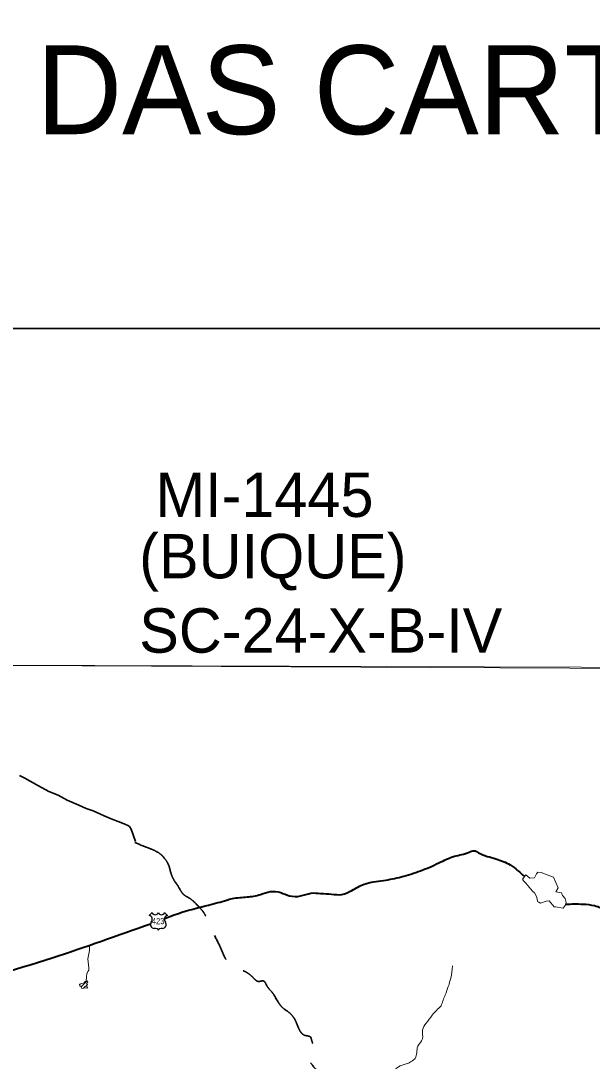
# Model space of a CAD drawing. Extents: x 553962 to 842807, y 8883888 to 9032388.
# Drawn here: x 599099 to 605530, y 8916524 to 8928234 of the extents above; entities that cross this region are included whole.
import ezdxf
from ezdxf.enums import TextEntityAlignment as Align

# ---------------------------------------------------------------- set-up
doc = ezdxf.new("R2010")
doc.units = 0
doc.header["$LTSCALE"] = 200
doc.linetypes.add('LONG_DASH_SHORT_DASH', pattern=[9.9, 6, -1.2, 1.5, -1.2])
doc.layers.add('6', color=7, linetype='Continuous', lineweight=13)

msp = doc.modelspace()

# ---------------------------------------------------------------- linework, layer by layer
at = {"layer": '6', "lineweight": 25}
for p, q in [((600544.7, 8918164.1), (600576.6, 8918196.1)), ((600716.5, 8918196.1), (600748.5, 8918164.1))]:
    msp.add_line(p, q, dxfattribs=at)
at = {"layer": '6'}
for p, q in [((599760.1, 8917384.1), (599770.4, 8917394.5)), ((599779.1, 8917360.8), (599843, 8917424.7)), ((599804.6, 8917343.8), (599848.1, 8917387.3)), ((599850.7, 8917347.5), (599851.7, 8917348.5))]:
    msp.add_line(p, q, dxfattribs=at)
at = {"layer": '6', "lineweight": 35}
msp.add_lwpolyline([(574695.3, 8924769.6), (626625.7, 8924769.6), (626625.7, 8896026.7), (574695.3, 8896026.7)], close=True, dxfattribs=at)
at = {"layer": '6'}
for points in [[(574684.9, 8921064.7), (596639.8, 8920989.8), (607636.3, 8920937.2), (626625.7, 8920820.5)], [(599871, 8917832.6), (599871.8, 8917767.7), (599854.5, 8917674.6), (599859.5, 8917608.7), (599864.6, 8917573), (599864.4, 8917548.3), (599853.3, 8917532), (599842.1, 8917507.4), (599836.4, 8917477.3), (599835.9, 8917422.3)]]:
    msp.add_lwpolyline(points, dxfattribs=at)
for points in [[(607600.8, 8920952.4), (596639.8, 8920989.8), (596608.8, 8909934.4), (607569.8, 8909894.9)], [(604784, 8918621.1), (604829.4, 8918582.7), (604881.8, 8918586.2), (604904.5, 8918633.3), (604918.5, 8918650.8), (604955.1, 8918647.3), (605023.2, 8918621.1), (605094.8, 8918593.2), (605145.5, 8918476.1), (605122.8, 8918430.7), (605183.9, 8918418.4), (605194.4, 8918387), (605225.8, 8918353.8), (605236.3, 8918310.1), (605227.6, 8918275.2), (605204.9, 8918247.2), (605115.8, 8918259.5), (605101.8, 8918261.2), (605044.2, 8918329.3), (605011, 8918325.8), (604949.9, 8918303.1), (604928.9, 8918311.9), (604913.2, 8918322.4), (604908, 8918371.3), (604880, 8918418.4), (604859.1, 8918435.9), (604784, 8918528.5), (604756, 8918553), (604745.5, 8918572.2)], [(599850.5, 8917427.2), (599834.3, 8917421.8), (599821.6, 8917421.3), (599813.8, 8917417.5), (599813.2, 8917405.3), (599758.2, 8917391.4), (599764.6, 8917366.4), (599775.7, 8917369.7), (599787.1, 8917340.2), (599836, 8917350.3), (599843.2, 8917350.2), (599852.5, 8917346.8), (599837.8, 8917375.8), (599849.5, 8917384.5), (599839.7, 8917403.4), (599853.1, 8917410)]]:
    msp.add_lwpolyline(points, close=True, dxfattribs=at)
at = {"layer": '6', "linetype": 'LONG_DASH_SHORT_DASH', "lineweight": 35}
msp.add_lwpolyline([(599084.4, 8919739.6), (599142.2, 8919708.2), (599298.2, 8919621.7), (599412.6, 8919560.7), (599519.3, 8919519.8), (599620.2, 8919462.1), (599750.1, 8919406.2), (599835.6, 8919368), (599912.8, 8919340.3), (600036.8, 8919285), (600114.6, 8919250.2), (600193.7, 8919219.8), (600262.6, 8919196), (600311.4, 8919174.3), (600323, 8919165.1), (600340.1, 8919135.3), (600389.9, 8918996.8)], dxfattribs=at)
at = {"layer": '6', "lineweight": 25}
for centre, radius, start, end in [((600611.6, 8918209.5), 37.4, 200.95927, 339.04073), ((600681.5, 8918209.5), 37.4, 200.95927, 339.04073), ((600532.2, 8918119.7), 46.1, 317.5721, 74.36886), ((600602.9, 8918062.7), 44.9, 144.73733, 264.65778), ((600690.2, 8918062.7), 44.9, 275.34222, 35.26267), ((600760.9, 8918119.7), 46.1, 105.62774, 222.4279), ((600598.5, 8917900), 118, 72.89371, 89.90057), ((600627.7, 8917994.7), 18.9, 357.69345, 72.92955), ((600665.4, 8917994.7), 18.9, 107.07045, 182.30655), ((600694.6, 8917900), 118, 90.09943, 107.10629)]:
    msp.add_arc(centre, radius, start, end, dxfattribs=at)
at = {"layer": '6', "lineweight": 40}
for points in [[(605233.4, 8918291.8), (605425.1, 8918291.8), (605556.8, 8918274.6), (605694.1, 8918217.3), (605780, 8918168.6), (605911.6, 8918165.8), (606008.9, 8918211.6), (606114.8, 8918211.6), (606197.8, 8918134.3), (606353.7, 8918138.6), (606551.2, 8918198.7), (606637.1, 8918198.7), (606903.2, 8918104.2), (607195.1, 8918130), (607418.3, 8918172.9), (607555.7, 8918130), (607658.7, 8918138.6), (607753.1, 8918172.9), (607813.2, 8918172.9), (607967.8, 8918353.3), (608139.5, 8918542.3), (608208.1, 8918748.4), (608345.5, 8918868.7), (608508.6, 8918946), (608680.3, 8919186.5), (608766.2, 8919298.2), (608826.3, 8919384.1), (608920.7, 8919409.8), (609058.1, 8919427), (609126.8, 8919444.2), (609186.8, 8919512.9), (609272.7, 8919538.7), (609418.7, 8919530.1), (609633.3, 8919581.6), (609805, 8919650.3), (609950.9, 8919727.6), (610174.2, 8919847.9), (610285.8, 8919890.8), (610500.4, 8919959.5), (610612, 8920002.5), (610715, 8920002.5), (610989.7, 8919925.2)], [(601410.6, 8918334.5), (601480.5, 8918354.8), (601646.5, 8918371.9), (601798.2, 8918400.6), (601906.9, 8918432.1), (602024.2, 8918420.6), (602124.4, 8918386.2), (602247.5, 8918383.4), (602364.8, 8918414.9), (602473.5, 8918412), (602596.6, 8918403.4), (602713.9, 8918400.6), (602825.5, 8918446.4), (602962.9, 8918515.1), (603180.4, 8918558), (603380.7, 8918598.1), (603598.2, 8918666.8), (603804.2, 8918755.6), (603978.8, 8918830), (604145.9, 8918875.8), (604200.3, 8918893), (604251.8, 8918870.1), (604446.4, 8918801.4), (604606.7, 8918732.7), (604769.8, 8918601)], [(600716.1, 8918129.4), (600909.4, 8918199.2), (601211.8, 8918280.7), (601418.4, 8918336.7)], [(596244.3, 8916699.1), (596768.6, 8916837.7), (598135.3, 8917279.9), (599449.7, 8917687.2), (600558.2, 8918071.1)]]:
    msp.add_spline(points, degree=3, dxfattribs=at)
at = {"layer": '6', "linetype": 'LONG_DASH_SHORT_DASH', "lineweight": 35}
msp.add_spline([(600381.6, 8918983.9), (600541.4, 8918921.3), (600673.5, 8918851.8), (600729.1, 8918789.3), (600763.8, 8918726.8), (600791.6, 8918629.5), (600819.4, 8918566.9), (600875, 8918483.6), (600930.6, 8918400.2), (601007, 8918351.5), (601076.5, 8918289), (601146, 8918212.6), (601243.3, 8918011), (601326.7, 8917844.3), (601389.2, 8917705.3), (601458.7, 8917601.1), (601549, 8917559.4), (601625.5, 8917531.6), (601715.8, 8917462.1), (601778.3, 8917420.4), (601827, 8917427.3), (601868.7, 8917371.8), (601924.2, 8917302.3), (602042.4, 8917128.5), (602132.7, 8917059.1), (602195.3, 8916968.7), (602237, 8916871.4), (602293.6, 8916815.3), (602362.3, 8916791.5), (602370.9, 8916763.8), (602382.4, 8916729.4), (602386.2, 8916632), (602375.9, 8916614.3), (602341.3, 8916526), (602362, 8916503.2), (602415.8, 8916437.2), (602443.5, 8916415.3), (602473.2, 8916343.3), (602487.1, 8916183.5), (602501, 8916086.2), (602528.4, 8916025.6), (602570.4, 8915982.6), (602548.4, 8915898.7), (602535.1, 8915867.2), (602486.4, 8915817.5), (602441.6, 8915736.4), (602464.5, 8915679.2), (602557, 8915738.3), (602710.7, 8915862.4), (602741.2, 8915892.9), (602862.4, 8915972.1), (603008.4, 8916103.8), (603086.7, 8916151.5), (603209.8, 8916155.7), (603293.2, 8916155.7)], degree=3, dxfattribs=at)
at = {"layer": '6'}
for points in [[(603828.9, 8917146.1), (603875.9, 8917271.5), (603938.5, 8917459.6), (603959.4, 8917595.5)], [(601609.2, 8914720.1), (601610.4, 8914757.2), (601607.5, 8914794.4), (601595.3, 8914840.8), (601588.3, 8914877.4), (601584.2, 8914897.8), (601587.2, 8914923.4), (601583.7, 8914959.4), (601575.5, 8914976.8), (601580.2, 8914990.7), (601580.2, 8915008.2), (601585.4, 8915021.5), (601583.1, 8915041.8), (601574.4, 8915045.9), (601573.2, 8915055.8), (601581.3, 8915069.7), (601597.6, 8915091.2), (601625.5, 8915115), (601652.7, 8915131.2), (601691.6, 8915149.2), (601715.4, 8915173), (601725.8, 8915195.1), (601729.3, 8915251.6), (601734, 8915267.3), (601750.8, 8915290.5), (601770.5, 8915312), (601789.1, 8915326), (601829.1, 8915341.6), (601860.5, 8915353.8), (601900.5, 8915378.2), (601947.5, 8915399.7), (601991.6, 8915429.9), (602050.8, 8915463.6), (602115.8, 8915492.6), (602158.7, 8915505.4), (602314.3, 8915536.7), (602476.2, 8915677.8), (602669.4, 8915813.7), (602862.7, 8915954.7), (603014.1, 8916106.3), (603097.7, 8916148.1), (603186.5, 8916137.6), (603238.7, 8916163.8), (603270, 8916247.4), (603290.9, 8916378), (603348.4, 8916461.6), (603437.2, 8916492.9), (603499.8, 8916524.3), (603536.4, 8916555.7), (603567.7, 8916691.5), (603620, 8916775.1), (603620, 8916874.4), (603661.7, 8916952.8), (603729.6, 8917041.6), (603828.9, 8917146.1)]]:
    msp.add_spline(points, degree=3, dxfattribs=at)

# ---------------------------------------------------------------- texts
msp.add_text('ARTICULAÇÃO DAS CARTAS 1:100.000', height=1000, dxfattribs=at).set_placement((601765.5, 8926958.2), align=Align.CENTER)
for s, p in [('MI-1445', (600615.8, 8922649.4)), ('(BUIQUE)', (600431.4, 8921958.8)), ('SC-24-X-B-IV', (600431.4, 8921121.7))]:
    msp.add_text(s, height=500, dxfattribs=at).set_placement(p)
at = {"layer": '6', "width": 0.75}
msp.add_text('423', height=70, dxfattribs=at).set_placement((600644.5, 8918065.8), align=Align.CENTER)

doc.saveas('drawing.dxf')
